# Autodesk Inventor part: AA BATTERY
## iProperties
Shininess: 20.0
Length Units: 11272
Angle Units: 11279
Time Units: 11290
Mass Units: 11283
Length Display Precision: 3
Angle Display Precision: 2
Created: 2001-03
Part Number: AA BATTERY
Document SubType Name: Modeling
Designer: Ron Crain
Catalog Web Link: http://www.arken.net
Density: 0.0
Volumn: 0.0
Area: 0.0
PropertySet Name: Model Information
Control State: 0
Master: False
Checked Out: False
Author: Ron
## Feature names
1. RevolutionFull1
2. Revolution2
3. Fillet1
4. Extrusion1
5. Extrusion2
